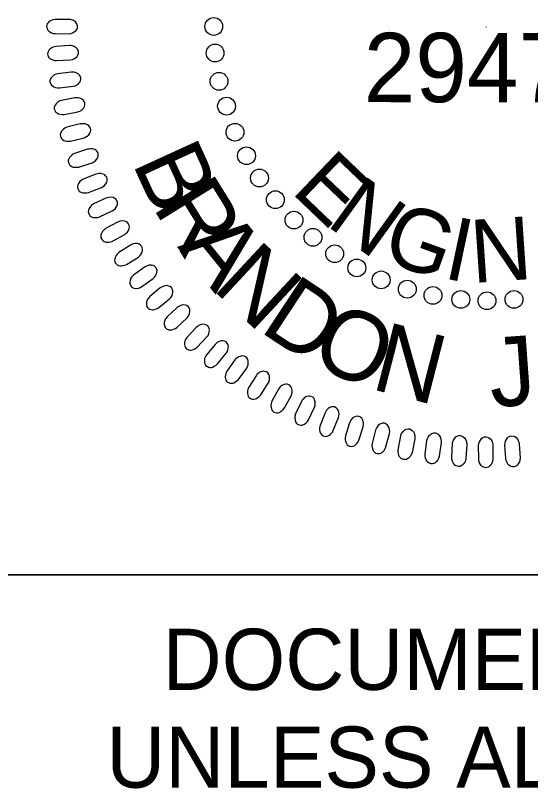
# Model space of a CAD drawing. Extents: x 505602 to 507286, y 483109 to 484209.
# Drawn here: x 507076.9 to 507123.2, y 484026.9 to 484096.5 of the extents above; entities that cross this region are included whole.
import ezdxf

# ---------------------------------------------------------------- set-up
doc = ezdxf.new("R2010")
doc.units = 0
for name, color, linetype in [('Sheet PE Seal Cell', 7, 'Continuous'), ('Sheet Profile CELL', 7, 'Continuous'), ('Sheet Sticker Exception Certification CELL', 7, 'Continuous')]:
    doc.layers.add(name, color=color, linetype=linetype)

msp = doc.modelspace()

# ---------------------------------------------------------------- linework, layer by layer
at = {"layer": 'Sheet PE Seal Cell'}
msp.add_line((507119.206, 484095.479), (507119.206, 484095.432), dxfattribs=at)
for points in [[(507081.659, 484096.141), (507080.432, 484096.142), (507080.213, 484096.104), (507080.073, 484096.052), (507079.904, 484095.94), (507079.794, 484095.843), (507079.714, 484095.73), (507079.674, 484095.626), (507079.654, 484095.514), (507079.674, 484095.402), (507079.704, 484095.282), (507079.763, 484095.178), (507079.864, 484095.073), (507079.943, 484095.013), (507080.093, 484094.946), (507080.273, 484094.886), (507080.432, 484094.864), (507081.689, 484094.856), (507081.858, 484094.878), (507081.998, 484094.923), (507082.157, 484095.013), (507082.297, 484095.125), (507082.377, 484095.222), (507082.437, 484095.379), (507082.457, 484095.528), (507082.416, 484095.678), (507082.367, 484095.782), (507082.268, 484095.91), (507082.098, 484096.029), (507081.918, 484096.096), (507081.789, 484096.126)], [(507081.712, 484093.784), (507080.487, 484093.707), (507080.271, 484093.656), (507080.134, 484093.596), (507079.972, 484093.473), (507079.868, 484093.369), (507079.796, 484093.252), (507079.763, 484093.145), (507079.75, 484093.032), (507079.777, 484092.922), (507079.815, 484092.804), (507079.88, 484092.703), (507079.987, 484092.605), (507080.07, 484092.55), (507080.223, 484092.493), (507080.406, 484092.444), (507080.566, 484092.431), (507081.822, 484092.503), (507081.99, 484092.536), (507082.126, 484092.589), (507082.279, 484092.689), (507082.412, 484092.809), (507082.486, 484092.911), (507082.536, 484093.071), (507082.546, 484093.222), (507082.497, 484093.369), (507082.44, 484093.47), (507082.333, 484093.591), (507082.157, 484093.699), (507081.973, 484093.755), (507081.842, 484093.777)], [(507081.876, 484091.403), (507080.659, 484091.25), (507080.446, 484091.185), (507080.314, 484091.116), (507080.16, 484090.983), (507080.063, 484090.873), (507079.998, 484090.752), (507079.972, 484090.643), (507079.966, 484090.529), (507080, 484090.421), (507080.044, 484090.306), (507080.116, 484090.209), (507080.229, 484090.118), (507080.316, 484090.068), (507080.472, 484090.02), (507080.658, 484089.983), (507080.819, 484089.981), (507082.067, 484090.131), (507082.232, 484090.174), (507082.365, 484090.236), (507082.512, 484090.345), (507082.636, 484090.473), (507082.704, 484090.58), (507082.743, 484090.743), (507082.744, 484090.894), (507082.686, 484091.038), (507082.623, 484091.135), (507082.509, 484091.249), (507082.326, 484091.346), (507082.139, 484091.39), (507082.007, 484091.404)], [(507082.21, 484089.077), (507081.004, 484088.848), (507080.796, 484088.77), (507080.669, 484088.693), (507080.523, 484088.55), (507080.433, 484088.435), (507080.376, 484088.31), (507080.356, 484088.2), (507080.358, 484088.086), (507080.398, 484087.979), (507080.45, 484087.868), (507080.528, 484087.776), (507080.646, 484087.692), (507080.735, 484087.648), (507080.895, 484087.609), (507081.083, 484087.584), (507081.243, 484087.592), (507082.479, 484087.82), (507082.642, 484087.874), (507082.771, 484087.944), (507082.91, 484088.062), (507083.027, 484088.198), (507083.087, 484088.309), (507083.116, 484088.474), (507083.108, 484088.625), (507083.041, 484088.764), (507082.972, 484088.858), (507082.85, 484088.963), (507082.662, 484089.049), (507082.472, 484089.082), (507082.34, 484089.086)], [(507082.689, 484086.736), (507081.501, 484086.432), (507081.298, 484086.341), (507081.175, 484086.256), (507081.039, 484086.105), (507080.957, 484085.983), (507080.907, 484085.855), (507080.895, 484085.744), (507080.903, 484085.63), (507080.95, 484085.527), (507081.009, 484085.418), (507081.093, 484085.332), (507081.216, 484085.255), (507081.308, 484085.216), (507081.469, 484085.189), (507081.658, 484085.176), (507081.818, 484085.193), (507083.037, 484085.498), (507083.196, 484085.562), (507083.32, 484085.64), (507083.452, 484085.767), (507083.56, 484085.91), (507083.613, 484086.023), (507083.632, 484086.191), (507083.614, 484086.341), (507083.538, 484086.475), (507083.464, 484086.564), (507083.336, 484086.663), (507083.142, 484086.736), (507082.951, 484086.757), (507082.818, 484086.754)], [(507083.343, 484084.452), (507082.176, 484084.073), (507081.979, 484083.97), (507081.862, 484083.878), (507081.735, 484083.718), (507081.661, 484083.592), (507081.62, 484083.461), (507081.615, 484083.349), (507081.63, 484083.236), (507081.684, 484083.136), (507081.749, 484083.031), (507081.838, 484082.95), (507081.966, 484082.882), (507082.059, 484082.849), (507082.223, 484082.831), (507082.412, 484082.83), (507082.571, 484082.858), (507083.768, 484083.239), (507083.922, 484083.313), (507084.042, 484083.398), (507084.165, 484083.533), (507084.263, 484083.682), (507084.31, 484083.8), (507084.318, 484083.967), (507084.291, 484084.116), (507084.207, 484084.246), (507084.127, 484084.33), (507083.993, 484084.42), (507083.795, 484084.481), (507083.603, 484084.49), (507083.471, 484084.478)], [(507084.102, 484082.215), (507082.961, 484081.764), (507082.77, 484081.648), (507082.659, 484081.549), (507082.543, 484081.382), (507082.477, 484081.251), (507082.444, 484081.117), (507082.446, 484081.006), (507082.468, 484080.894), (507082.528, 484080.798), (507082.6, 484080.697), (507082.693, 484080.622), (507082.825, 484080.561), (507082.921, 484080.535), (507083.086, 484080.527), (507083.274, 484080.538), (507083.431, 484080.575), (507084.602, 484081.03), (507084.752, 484081.114), (507084.865, 484081.207), (507084.98, 484081.349), (507085.069, 484081.505), (507085.108, 484081.624), (507085.105, 484081.792), (507085.069, 484081.939), (507084.977, 484082.063), (507084.892, 484082.142), (507084.753, 484082.224), (507084.551, 484082.272), (507084.359, 484082.269), (507084.228, 484082.248)], [(507085.001, 484080.056), (507083.891, 484079.534), (507083.709, 484079.406), (507083.604, 484079.3), (507083.499, 484079.126), (507083.441, 484078.991), (507083.416, 484078.856), (507083.425, 484078.744), (507083.454, 484078.634), (507083.52, 484078.542), (507083.598, 484078.446), (507083.697, 484078.377), (507083.832, 484078.325), (507083.929, 484078.304), (507084.093, 484078.307), (507084.281, 484078.33), (507084.435, 484078.377), (507085.576, 484078.905), (507085.719, 484078.998), (507085.827, 484079.097), (507085.932, 484079.246), (507086.012, 484079.407), (507086.043, 484079.529), (507086.03, 484079.697), (507085.984, 484079.841), (507085.884, 484079.959), (507085.794, 484080.032), (507085.651, 484080.105), (507085.446, 484080.14), (507085.255, 484080.126), (507085.125, 484080.097)], [(507086.049, 484077.907), (507084.973, 484077.316), (507084.799, 484077.178), (507084.702, 484077.065), (507084.607, 484076.885), (507084.558, 484076.747), (507084.542, 484076.61), (507084.557, 484076.499), (507084.594, 484076.391), (507084.666, 484076.303), (507084.75, 484076.213), (507084.852, 484076.15), (507084.99, 484076.106), (507085.089, 484076.092), (507085.252, 484076.105), (507085.438, 484076.139), (507085.589, 484076.196), (507086.694, 484076.794), (507086.832, 484076.896), (507086.932, 484077.003), (507087.029, 484077.158), (507087.097, 484077.323), (507087.121, 484077.447), (507087.097, 484077.613), (507087.043, 484077.754), (507086.936, 484077.866), (507086.842, 484077.934), (507086.693, 484077.997), (507086.487, 484078.02), (507086.297, 484077.993), (507086.169, 484077.956)], [(507087.205, 484075.832), (507086.169, 484075.175), (507086.003, 484075.026), (507085.914, 484074.908), (507085.83, 484074.722), (507085.79, 484074.581), (507085.783, 484074.443), (507085.805, 484074.334), (507085.848, 484074.228), (507085.926, 484074.145), (507086.015, 484074.06), (507086.121, 484074.003), (507086.261, 484073.968), (507086.36, 484073.96), (507086.523, 484073.984), (507086.707, 484074.03), (507086.853, 484074.096), (507087.919, 484074.762), (507088.05, 484074.872), (507088.144, 484074.986), (507088.23, 484075.146), (507088.288, 484075.316), (507088.304, 484075.441), (507088.27, 484075.605), (507088.207, 484075.742), (507088.093, 484075.847), (507087.995, 484075.908), (507087.842, 484075.963), (507087.635, 484075.973), (507087.447, 484075.933), (507087.322, 484075.889)], [(507088.482, 484073.858), (507087.488, 484073.136), (507087.333, 484072.977), (507087.25, 484072.853), (507087.179, 484072.663), (507087.148, 484072.519), (507087.149, 484072.382), (507087.178, 484072.274), (507087.228, 484072.171), (507087.31, 484072.092), (507087.405, 484072.013), (507087.515, 484071.963), (507087.657, 484071.938), (507087.756, 484071.936), (507087.917, 484071.969), (507088.097, 484072.026), (507088.24, 484072.102), (507089.261, 484072.834), (507089.385, 484072.952), (507089.471, 484073.071), (507089.548, 484073.237), (507089.595, 484073.409), (507089.603, 484073.535), (507089.559, 484073.697), (507089.487, 484073.83), (507089.367, 484073.927), (507089.265, 484073.983), (507089.11, 484074.028), (507088.903, 484074.024), (507088.717, 484073.973), (507088.595, 484073.922)], [(507089.885, 484071.976), (507088.939, 484071.194), (507088.794, 484071.026), (507088.72, 484070.897), (507088.661, 484070.702), (507088.638, 484070.557), (507088.648, 484070.42), (507088.684, 484070.314), (507088.74, 484070.215), (507088.827, 484070.141), (507088.926, 484070.068), (507089.039, 484070.025), (507089.182, 484070.009), (507089.282, 484070.013), (507089.44, 484070.057), (507089.616, 484070.125), (507089.754, 484070.209), (507090.727, 484071.004), (507090.844, 484071.129), (507090.922, 484071.253), (507090.988, 484071.424), (507091.025, 484071.599), (507091.024, 484071.725), (507090.97, 484071.884), (507090.89, 484072.012), (507090.764, 484072.101), (507090.659, 484072.15), (507090.501, 484072.185), (507090.295, 484072.17), (507090.113, 484072.107), (507089.994, 484072.047)], [(507091.395, 484070.205), (507090.5, 484069.366), (507090.366, 484069.189), (507090.3, 484069.055), (507090.253, 484068.857), (507090.24, 484068.711), (507090.258, 484068.575), (507090.301, 484068.471), (507090.363, 484068.376), (507090.454, 484068.308), (507090.558, 484068.241), (507090.673, 484068.206), (507090.818, 484068.198), (507090.916, 484068.209), (507091.072, 484068.262), (507091.244, 484068.341), (507091.375, 484068.434), (507092.296, 484069.288), (507092.405, 484069.421), (507092.476, 484069.549), (507092.531, 484069.723), (507092.556, 484069.901), (507092.548, 484070.026), (507092.484, 484070.182), (507092.396, 484070.304), (507092.265, 484070.386), (507092.157, 484070.428), (507091.997, 484070.453), (507091.792, 484070.424), (507091.614, 484070.35), (507091.5, 484070.283)], [(507093.131, 484068.427), (507092.29, 484067.533), (507092.167, 484067.348), (507092.11, 484067.21), (507092.075, 484067.01), (507092.071, 484066.862), (507092.098, 484066.728), (507092.147, 484066.628), (507092.215, 484066.536), (507092.31, 484066.474), (507092.419, 484066.414), (507092.535, 484066.386), (507092.68, 484066.387), (507092.778, 484066.404), (507092.93, 484066.467), (507093.096, 484066.557), (507093.222, 484066.657), (507094.088, 484067.569), (507094.187, 484067.707), (507094.25, 484067.84), (507094.294, 484068.018), (507094.308, 484068.196), (507094.292, 484068.32), (507094.219, 484068.472), (507094.123, 484068.589), (507093.987, 484068.662), (507093.876, 484068.697), (507093.716, 484068.712), (507093.513, 484068.67), (507093.34, 484068.585), (507093.23, 484068.511)], [(507094.821, 484066.897), (507094.038, 484065.952), (507093.927, 484065.759), (507093.878, 484065.618), (507093.856, 484065.416), (507093.862, 484065.269), (507093.897, 484065.136), (507093.952, 484065.039), (507094.026, 484064.952), (507094.124, 484064.897), (507094.236, 484064.843), (507094.354, 484064.822), (507094.499, 484064.833), (507094.596, 484064.855), (507094.743, 484064.928), (507094.903, 484065.028), (507095.023, 484065.137), (507095.83, 484066.1), (507095.921, 484066.245), (507095.974, 484066.382), (507096.008, 484066.561), (507096.011, 484066.74), (507095.986, 484066.864), (507095.903, 484067.01), (507095.801, 484067.121), (507095.661, 484067.185), (507095.547, 484067.213), (507095.386, 484067.218), (507095.187, 484067.163), (507095.019, 484067.068), (507094.914, 484066.987)], [(507096.601, 484065.497), (507095.88, 484064.504), (507095.781, 484064.305), (507095.741, 484064.161), (507095.732, 484063.958), (507095.747, 484063.811), (507095.79, 484063.681), (507095.851, 484063.588), (507095.93, 484063.505), (507096.033, 484063.456), (507096.148, 484063.41), (507096.267, 484063.396), (507096.41, 484063.416), (507096.506, 484063.444), (507096.648, 484063.527), (507096.802, 484063.636), (507096.914, 484063.752), (507097.659, 484064.764), (507097.74, 484064.914), (507097.786, 484065.054), (507097.808, 484065.235), (507097.8, 484065.415), (507097.767, 484065.536), (507097.676, 484065.677), (507097.566, 484065.781), (507097.422, 484065.837), (507097.308, 484065.857), (507097.147, 484065.852), (507096.95, 484065.785), (507096.79, 484065.679), (507096.69, 484065.592)], [(507098.503, 484064.083), (507097.846, 484063.047), (507097.759, 484062.842), (507097.728, 484062.696), (507097.732, 484062.493), (507097.756, 484062.349), (507097.808, 484062.221), (507097.874, 484062.131), (507097.959, 484062.055), (507098.063, 484062.011), (507098.181, 484061.972), (507098.301, 484061.967), (507098.443, 484061.995), (507098.536, 484062.03), (507098.673, 484062.12), (507098.82, 484062.239), (507098.924, 484062.362), (507099.604, 484063.419), (507099.676, 484063.574), (507099.713, 484063.716), (507099.723, 484063.899), (507099.703, 484064.077), (507099.663, 484064.196), (507099.564, 484064.331), (507099.448, 484064.428), (507099.3, 484064.474), (507099.185, 484064.488), (507099.025, 484064.473), (507098.833, 484064.394), (507098.679, 484064.278), (507098.585, 484064.185)], [(507100.521, 484062.868), (507099.93, 484061.793), (507099.857, 484061.583), (507099.835, 484061.435), (507099.852, 484061.233), (507099.884, 484061.089), (507099.944, 484060.965), (507100.016, 484060.88), (507100.105, 484060.808), (507100.212, 484060.772), (507100.332, 484060.741), (507100.452, 484060.742), (507100.592, 484060.78), (507100.683, 484060.82), (507100.814, 484060.919), (507100.953, 484061.048), (507101.05, 484061.177), (507101.662, 484062.274), (507101.723, 484062.433), (507101.751, 484062.578), (507101.75, 484062.76), (507101.72, 484062.937), (507101.673, 484063.054), (507101.564, 484063.182), (507101.442, 484063.271), (507101.292, 484063.308), (507101.176, 484063.315), (507101.017, 484063.289), (507100.831, 484063.198), (507100.685, 484063.073), (507100.596, 484062.974)], [(507102.58, 484061.761), (507102.058, 484060.651), (507101.998, 484060.437), (507101.986, 484060.289), (507102.015, 484060.087), (507102.056, 484059.946), (507102.124, 484059.827), (507102.201, 484059.746), (507102.295, 484059.68), (507102.404, 484059.651), (507102.525, 484059.627), (507102.645, 484059.636), (507102.783, 484059.682), (507102.871, 484059.728), (507102.995, 484059.835), (507103.126, 484059.972), (507103.215, 484060.107), (507103.757, 484061.24), (507103.808, 484061.404), (507103.827, 484061.549), (507103.814, 484061.731), (507103.773, 484061.906), (507103.718, 484062.019), (507103.602, 484062.14), (507103.474, 484062.222), (507103.323, 484062.25), (507103.206, 484062.249), (507103.049, 484062.213), (507102.869, 484062.111), (507102.732, 484061.976), (507102.65, 484061.872)], [(507104.708, 484060.753), (507104.256, 484059.612), (507104.21, 484059.395), (507104.207, 484059.246), (507104.249, 484059.046), (507104.298, 484058.909), (507104.374, 484058.794), (507104.456, 484058.718), (507104.553, 484058.658), (507104.664, 484058.635), (507104.787, 484058.619), (507104.906, 484058.635), (507105.04, 484058.691), (507105.125, 484058.742), (507105.243, 484058.857), (507105.364, 484059.001), (507105.444, 484059.141), (507105.914, 484060.307), (507105.956, 484060.473), (507105.965, 484060.619), (507105.941, 484060.8), (507105.888, 484060.971), (507105.827, 484061.082), (507105.703, 484061.195), (507105.571, 484061.269), (507105.418, 484061.286), (507105.302, 484061.278), (507105.147, 484061.233), (507104.974, 484061.119), (507104.845, 484060.977), (507104.77, 484060.868)], [(507106.917, 484059.851), (507106.537, 484058.684), (507106.505, 484058.464), (507106.511, 484058.315), (507106.565, 484058.119), (507106.624, 484057.985), (507106.706, 484057.874), (507106.793, 484057.804), (507106.894, 484057.75), (507107.006, 484057.735), (507107.13, 484057.726), (507107.247, 484057.75), (507107.378, 484057.814), (507107.459, 484057.871), (507107.57, 484057.992), (507107.682, 484058.144), (507107.753, 484058.289), (507108.149, 484059.481), (507108.18, 484059.65), (507108.18, 484059.797), (507108.144, 484059.976), (507108.081, 484060.143), (507108.013, 484060.249), (507107.882, 484060.355), (507107.746, 484060.42), (507107.592, 484060.428), (507107.477, 484060.413), (507107.325, 484060.358), (507107.159, 484060.234), (507107.039, 484060.083), (507106.971, 484059.969)], [(507109.25, 484059.178), (507108.944, 484057.99), (507108.926, 484057.769), (507108.941, 484057.62), (507109.008, 484057.427), (507109.074, 484057.297), (507109.164, 484057.192), (507109.255, 484057.127), (507109.358, 484057.08), (507109.472, 484057.072), (507109.595, 484057.071), (507109.711, 484057.102), (507109.837, 484057.173), (507109.915, 484057.235), (507110.018, 484057.364), (507110.12, 484057.523), (507110.182, 484057.672), (507110.502, 484058.887), (507110.522, 484059.056), (507110.513, 484059.203), (507110.466, 484059.38), (507110.393, 484059.543), (507110.318, 484059.644), (507110.181, 484059.742), (507110.042, 484059.798), (507109.886, 484059.797), (507109.773, 484059.774), (507109.625, 484059.71), (507109.467, 484059.575), (507109.357, 484059.417), (507109.296, 484059.3)], [(507112.772, 484058.39), (507112.541, 484057.185), (507112.463, 484056.977), (507112.386, 484056.849), (507112.244, 484056.704), (507112.128, 484056.615), (507112.003, 484056.557), (507111.892, 484056.537), (507111.778, 484056.539), (507111.673, 484056.58), (507111.56, 484056.632), (507111.469, 484056.71), (507111.385, 484056.827), (507111.341, 484056.917), (507111.303, 484057.077), (507111.278, 484057.264), (507111.286, 484057.425), (507111.514, 484058.661), (507111.568, 484058.823), (507111.639, 484058.952), (507111.757, 484059.092), (507111.893, 484059.208), (507112.003, 484059.268), (507112.168, 484059.297), (507112.32, 484059.288), (507112.458, 484059.221), (507112.552, 484059.153), (507112.658, 484059.032), (507112.743, 484058.842), (507112.776, 484058.653), (507112.781, 484058.521)], [(507115.138, 484058.064), (507114.983, 484056.847), (507114.919, 484056.634), (507114.849, 484056.502), (507114.717, 484056.348), (507114.607, 484056.251), (507114.485, 484056.186), (507114.377, 484056.16), (507114.263, 484056.154), (507114.155, 484056.188), (507114.039, 484056.233), (507113.943, 484056.305), (507113.852, 484056.418), (507113.802, 484056.504), (507113.754, 484056.661), (507113.718, 484056.846), (507113.715, 484057.008), (507113.866, 484058.255), (507113.909, 484058.42), (507113.972, 484058.554), (507114.08, 484058.7), (507114.209, 484058.825), (507114.316, 484058.892), (507114.479, 484058.932), (507114.63, 484058.932), (507114.773, 484058.874), (507114.871, 484058.811), (507114.985, 484058.697), (507115.081, 484058.514), (507115.126, 484058.327), (507115.139, 484058.194)], [(507117.455, 484057.867), (507117.377, 484056.642), (507117.326, 484056.426), (507117.265, 484056.29), (507117.143, 484056.127), (507117.039, 484056.023), (507116.922, 484055.952), (507116.815, 484055.918), (507116.701, 484055.906), (507116.591, 484055.933), (507116.474, 484055.97), (507116.373, 484056.036), (507116.275, 484056.143), (507116.22, 484056.226), (507116.162, 484056.379), (507116.114, 484056.562), (507116.102, 484056.723), (507116.173, 484057.978), (507116.207, 484058.145), (507116.261, 484058.282), (507116.36, 484058.435), (507116.48, 484058.568), (507116.583, 484058.641), (507116.743, 484058.691), (507116.894, 484058.701), (507117.041, 484058.652), (507117.141, 484058.596), (507117.262, 484058.488), (507117.37, 484058.311), (507117.427, 484058.127), (507117.448, 484057.997)], [(507119.808, 484057.795), (507119.808, 484056.568), (507119.77, 484056.349), (507119.718, 484056.209), (507119.606, 484056.039), (507119.508, 484055.93), (507119.396, 484055.85), (507119.292, 484055.81), (507119.18, 484055.791), (507119.068, 484055.81), (507118.948, 484055.84), (507118.843, 484055.9), (507118.738, 484056), (507118.679, 484056.08), (507118.611, 484056.23), (507118.552, 484056.409), (507118.529, 484056.569), (507118.522, 484057.825), (507118.545, 484057.994), (507118.59, 484058.134), (507118.679, 484058.294), (507118.791, 484058.433), (507118.889, 484058.513), (507119.046, 484058.573), (507119.196, 484058.593), (507119.345, 484058.553), (507119.45, 484058.503), (507119.577, 484058.404), (507119.696, 484058.234), (507119.764, 484058.054), (507119.793, 484057.924)], [(507122.175, 484057.917), (507122.251, 484056.693), (507122.228, 484056.472), (507122.185, 484056.329), (507122.083, 484056.152), (507121.994, 484056.037), (507121.886, 484055.951), (507121.785, 484055.904), (507121.674, 484055.877), (507121.561, 484055.891), (507121.44, 484055.913), (507121.331, 484055.966), (507121.22, 484056.059), (507121.156, 484056.135), (507121.08, 484056.28), (507121.009, 484056.455), (507120.976, 484056.613), (507120.89, 484057.867), (507120.902, 484058.038), (507120.938, 484058.18), (507121.018, 484058.344), (507121.121, 484058.491), (507121.213, 484058.576), (507121.366, 484058.646), (507121.514, 484058.675), (507121.665, 484058.645), (507121.773, 484058.602), (507121.906, 484058.51), (507122.036, 484058.348), (507122.115, 484058.173), (507122.153, 484058.046)]]:
    msp.add_lwpolyline(points, close=True, dxfattribs=at)
for centre in [(507094.698, 484095.506), (507094.817, 484093.115), (507095.174, 484090.566), (507095.85, 484088.335), (507096.606, 484085.984), (507097.641, 484083.872), (507098.81, 484081.868), (507100.242, 484079.916), (507101.914, 484078.083), (507103.625, 484076.529), (507105.576, 484075.054), (507107.566, 484073.779), (507109.755, 484072.702), (507112.104, 484071.865), (507114.413, 484071.307), (507116.921, 484070.947), (507119.27, 484070.827), (507121.699, 484070.946)]:
    msp.add_circle(centre, 0.801, dxfattribs=at)
at = {"layer": 'Sheet Profile CELL'}
msp.add_lwpolyline([(507069.03, 484158.662), (507169.08, 484158.662), (507169.08, 484046.162), (507069.03, 484046.162)], close=True, dxfattribs=at)
at = {"layer": 'Sheet Sticker Exception Certification CELL'}
msp.add_line((507069.03, 484046.162), (507269.067, 484046.162), dxfattribs=at)
msp.add_line((507069.03, 484046.162), (507269.067, 484046.162), dxfattribs=at)

# ---------------------------------------------------------------- texts
at = {"layer": 'Sheet PE Seal Cell'}
for s, height, rotation, p in [('29470', 6.2363, 359.98136, (507108.193, 484088.694)), ('B', 6.236, 294.5897, (507087.323, 484083.255)), ('E', 5.669, 316.26559, (507101.563, 484080.634)), ('R', 6.236, 301.86473, (507089.134, 484079.299)), ('N', 5.669, 324.20538, (507104.698, 484077.679)), ('G', 5.669, 340.08498, (507109.592, 484074.58)), ('I', 5.669, 348.02477, (507115.221, 484072.891)), ('N', 5.669, 3.90437, (507117.974, 484072.418)), ('A', 6.236, 308.98157, (507091.377, 484075.681)), ('N', 6.236, 317.09274, (507094.456, 484071.933)), ('D', 6.236, 326.58243, (507098.686, 484068.152)), ('O', 6.236, 335.45066, (507103.152, 484065.293)), ('N', 6.236, 345.5505, (507108.704, 484062.922)), ('J', 6.236, 4.1457, (507119.655, 484061.23))]:
    msp.add_text(s, height=height, rotation=rotation, dxfattribs=at).set_placement(p)
at = {"layer": 'Sheet Sticker Exception Certification CELL'}
for s, p in [('DOCUMENT NOT CONSIDERED FINAL', (507090.101, 484035.816)), ('DOCUMENT NOT CONSIDERED FINAL', (507090.101, 484035.816)), ('UNLESS ALL SIGNATURES COMPLETED', (507085.03, 484027.016)), ('UNLESS ALL SIGNATURES COMPLETED', (507085.03, 484027.016))]:
    msp.add_text(s, height=5.5, dxfattribs=at).set_placement(p)

doc.saveas('drawing.dxf')
